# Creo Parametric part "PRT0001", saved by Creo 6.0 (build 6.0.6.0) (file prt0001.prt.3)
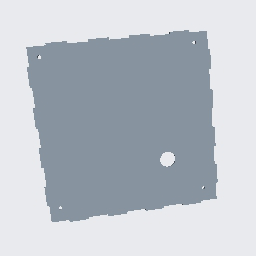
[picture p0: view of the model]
Units: Inch lbm Second (Pro/E Default); INCH, POUND, SECS

Created from: INLBS_PART_SOLID.PRT

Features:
  1. datum plane "RIGHT"
  2. datum plane "TOP"
  3. datum plane "FRONT"
  4. coordinate system
  5. sketch "Sketch 1"
  6. extrusion "Extrude 1"
  7. sketch "Sketch 2"
  8. extruded cut "Extrude 2"
  9. sketch "Sketch 3"
  10. extruded cut "Extrude 3"
  11. sketch "Sketch 4"
  12. extruded cut "Extrude 4"

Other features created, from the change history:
  extrusion "Extrude 2" (2 times)
  mirror "Mirror 1"

Surfaces: 70 plane, 5 cylinder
